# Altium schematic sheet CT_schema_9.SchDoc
size 387 x 278 mm
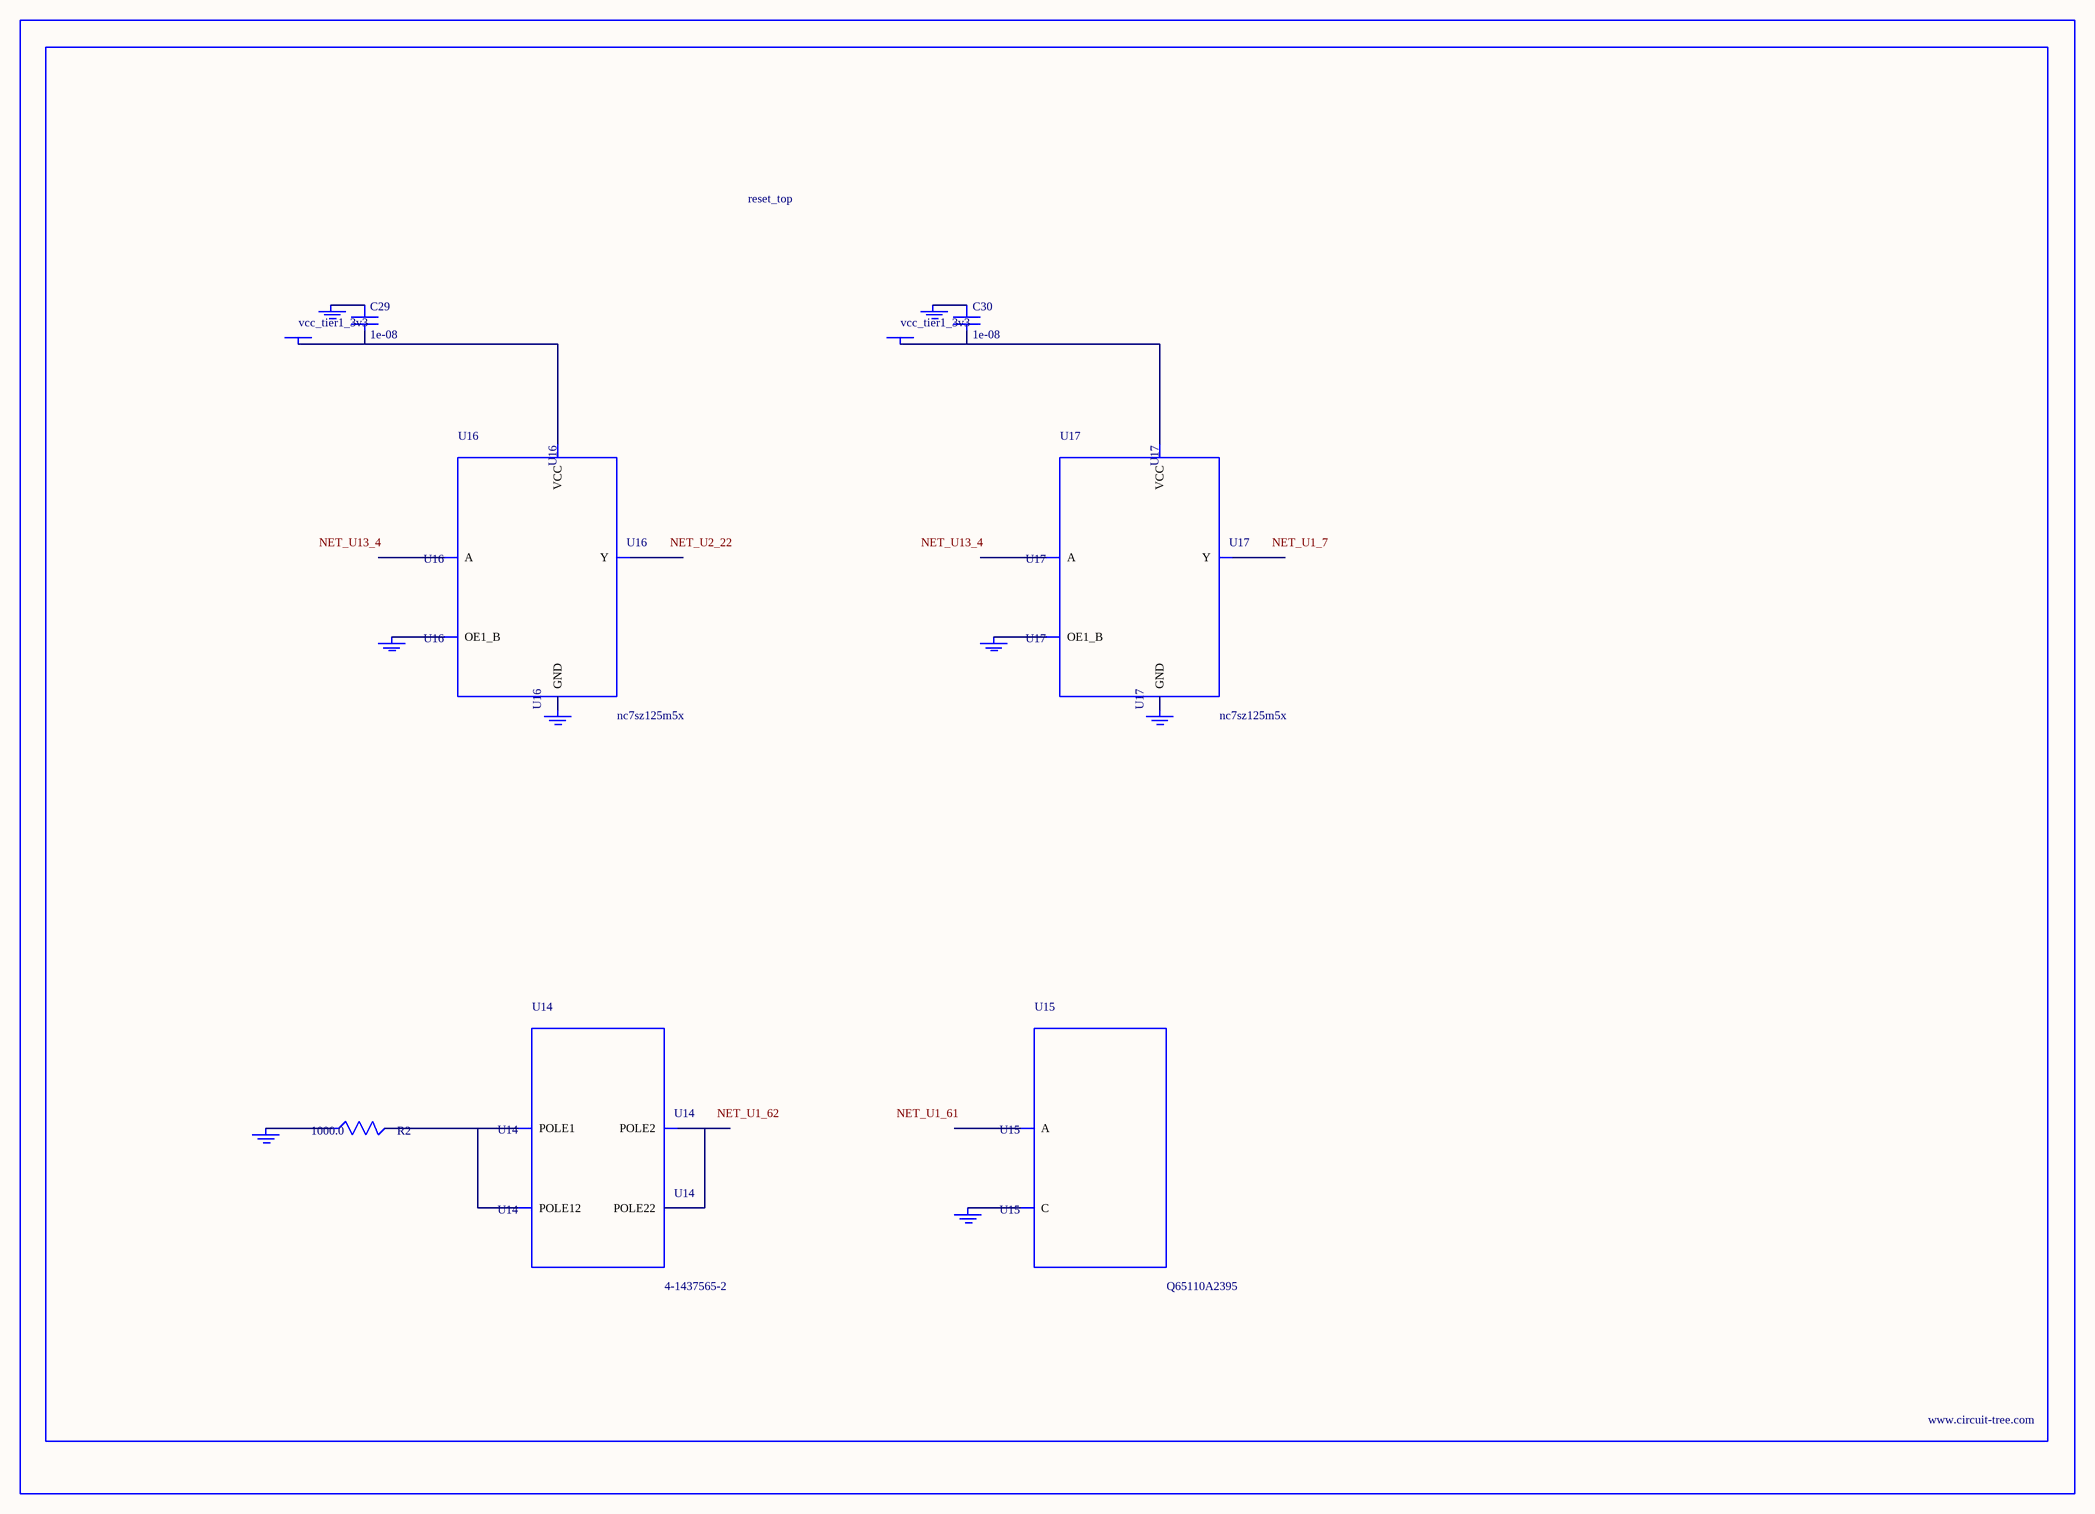
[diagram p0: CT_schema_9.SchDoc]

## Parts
BORDER8  (no value)
C29  1e-08  [C0402]
C30  1e-08  [C0402]
GND_INSTANCE_8_0  (no value)
GND_INSTANCE_8_1  (no value)
GND_INSTANCE_8_2  (no value)
GND_INSTANCE_8_3  (no value)
GND_INSTANCE_8_4  (no value)
GND_INSTANCE_8_5  (no value)
GND_INSTANCE_8_6  (no value)
GND_INSTANCE_8_7  (no value)
POWER_INSTANCE_8_0  vcc_tier1_3v3
POWER_INSTANCE_8_1  vcc_tier1_3v3
R2  1000.0  [R0603]
U14  4-1437565-2  [SW_4-1437565-2]
U15  Q65110A2395  [LGM67K-G1J2-24-Z]
U16  nc7sz125m5x  [NC7SZ125M5X]
U17  nc7sz125m5x  [NC7SZ125M5X]

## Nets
NetC29_1: C29.1 GND_INSTANCE_8_2.0(GND)
NetC29_2: C29.2 POWER_INSTANCE_8_0.0(PWR) U16.5(VCC)
NetC30_1: C30.1 GND_INSTANCE_8_5.0(GND)
NetC30_2: C30.2 POWER_INSTANCE_8_1.0(PWR) U17.5(VCC)
NetGND_INSTANCE_8_0_0: GND_INSTANCE_8_0.0(GND) R2.1
NetGND_INSTANCE_8_1_0: GND_INSTANCE_8_1.0(GND) U15.C
NetGND_INSTANCE_8_3_0: GND_INSTANCE_8_3.0(GND) U16.1(OE1_B)
NetGND_INSTANCE_8_4_0: GND_INSTANCE_8_4.0(GND) U16.3(GND)
NetGND_INSTANCE_8_6_0: GND_INSTANCE_8_6.0(GND) U17.1(OE1_B)
NetGND_INSTANCE_8_7_0: GND_INSTANCE_8_7.0(GND) U17.3(GND)
NetR2_2: R2.2 U14.1(POLE1) U14.2(POLE12)
NetU14_3: U14.3(POLE2) U14.4(POLE22)

Not connected (* = marked no-connect by the designer): U15 A; U16 2(A) 4(Y); U17 2(A) 4(Y)

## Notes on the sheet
- Labels drawn without touching a wire or pin: NET_U1_7, NET_U1_61, NET_U1_62, NET_U2_22, NET_U13_4

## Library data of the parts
BORDER8 = BORDER_PAGE8
C29 C30 = C0402C103K3RAC
GND_INSTANCE_8_0-GND_INSTANCE_8_7 = GND
POWER_INSTANCE_8_0 POWER_INSTANCE_8_1 = PWR
R2 = RC0603JR-071KL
